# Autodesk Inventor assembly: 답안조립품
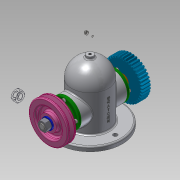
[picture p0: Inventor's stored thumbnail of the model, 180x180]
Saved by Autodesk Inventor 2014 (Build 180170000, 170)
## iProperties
Created: 2019-11
Part Number: 답안조립품
Document SubType Name: Assembly
Designer: net
Author: net
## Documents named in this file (14)
- C:\Users\net\Desktop\491104V1049\답안조립품.iam
- C:\Users\net\Desktop\491104V1049\답안본체.ipt
- C:\Users\net\Desktop\491104V1049\축.ipt
- C:\Users\net\Desktop\491104V1049\베어링 6203.ipt
- C:\Users\net\Desktop\491104V1049\커버.ipt
- C:\Users\net\Desktop\491104V1049\부시.ipt
- C:\Users\net\Desktop\491104V1049\오일 실 26 38 8.ipt
- C:\Users\net\Desktop\491104V1049\볼트 M4.ipt
- C:\Users\net\Desktop\491104V1049\키 5x5x12.ipt
- C:\Users\net\Desktop\491104V1049\V-벨트풀리.ipt
- V-벨트풀리.ipt
- C:\Users\net\Desktop\491104V1049\스퍼기어.ipt
- C:\Users\net\Desktop\491104V1049\와셔 12x24.ipt
- C:\Users\net\Desktop\491104V1049\너트 M12x1.25.ipt
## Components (1 placed, 1 different names)
1. V-벨트풀리:1
